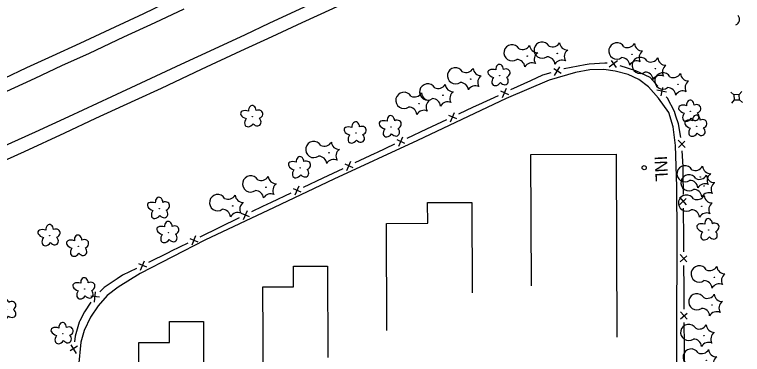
# Model space of a CAD drawing. Extents: x 588843 to 2552415, y 180129 to 269402.
# Drawn here: x 593421.1 to 593773.6, y 187938.5 to 188103.3 of the extents above; entities that cross this region are included whole.
import ezdxf

# ---------------------------------------------------------------- set-up
doc = ezdxf.new("R2010")
doc.units = 0
for name, color, linetype in [('Default', 7, 'Continuous'), ('E_BLD', 7, 'Continuous'), ('E_DRN', 7, 'Continuous'), ('E_DRN_Text', 7, 'Continuous'), ('E_DWY', 7, 'Continuous'), ('E_FEN_P', 7, 'Continuous'), ('E_LAND_Vegetation', 7, 'Continuous'), ('E_RDWY', 7, 'Continuous'), ('E_RDWY_Gravel', 7, 'Continuous'), ('E_UTL_AG_Bold', 7, 'Continuous')]:
    doc.layers.add(name, color=color, linetype=linetype)

# ---------------------------------------------------------------- blocks, each defined once
blk = doc.blocks.new('DTRE')
at = {"layer": 'Default'}
blk.add_circle((-0.18, 0), 0.183, dxfattribs=at)
for centre, major_axis, ratio in [((-1.87, 5.32), (1.36, -4.98), 0.782863), ((4.06, 2.74), (-5.27, -2.93), 0.691916), ((-5.87, 0.15), (4.93, -0.12), 0.832022), ((-2.49, -5.24), (1.8, 4.86), 0.716896), ((3.54, -3.71), (-5.01, 4.58), 0.560249)]:
    blk.add_ellipse(centre, major_axis=major_axis, ratio=ratio, start_param=1.570796, end_param=4.712389, dxfattribs=at)
blk = doc.blocks.new('CTRE')
at = {"layer": 'Default'}
blk.add_circle((0, 0), 0.223, dxfattribs=at)
for centre, start, end in [((-11.97, 8.96), 280.2067, 5.97162), ((1.81, 14.92), 220.21132, 305.97623), ((13.83, 5.89), 160.21133, 245.97624), ((-13.83, -5.9), 340.21132, 65.97623), ((12.03, -9.04), 185.92721, 100.25111), ((-1.81, -14.93), 40.21133, 125.97624)]:
    blk.add_arc(centre, 7.87, start, end, dxfattribs=at)
blk = doc.blocks.new('CULV2')
at = {"layer": 'E_DRN'}
blk.add_arc((19.7, 14.8), 24.6, 216.8699, 323.1301, dxfattribs=at)
blk = doc.blocks.new('PED')
at = {"layer": 'Default'}
for p, q in [((-2.5, 2.5), (-5.33, 5.33)), ((2.5, 2.5), (5.33, 5.33)), ((-2.5, -2.5), (-5.33, -5.33)), ((2.5, -2.5), (5.33, -5.33))]:
    blk.add_line(p, q, dxfattribs=at)
blk.add_lwpolyline([(-2.5, -2.5), (2.5, -2.5), (2.5, 2.5), (-2.5, 2.5)], close=True, dxfattribs=at)
blk = doc.blocks.new('INLT_38')
at = {"layer": 'E_DRN_Text'}
blk.add_text('INL', height=12, dxfattribs=at).set_placement((-11.03, -6))

msp = doc.modelspace()

# ---------------------------------------------------------------- linework, layer by layer
at = {"layer": 'E_BLD'}
for points in [[(593671.39, 187971.86), (593671.13, 188035.51), (593712.46, 188035.68), (593712.81, 187946.87)], [(593601.38, 187950.19), (593601.15, 188002.09), (593621.17, 188002.18), (593621.12, 188012.15), (593642.47, 188012.24), (593642.66, 187968.48)], [(593541.59, 187922.43), (593541.42, 187971.31), (593556.2, 187971.36), (593556.17, 187981.35), (593572.64, 187981.4), (593572.79, 187937.03)], [(593481.51, 187894.33), (593481.28, 187944.27), (593496.19, 187944.33), (593496.14, 187954.5), (593512.56, 187954.57), (593512.76, 187908.95)]]:
    msp.add_lwpolyline(points, dxfattribs=at)
at = {"layer": 'E_DRN'}
msp.add_ellipse((593725.99, 188029.11), major_axis=(-0.936, 0.363), ratio=0.999898, dxfattribs=at)
at = {"layer": 'E_DWY'}
msp.add_lwpolyline([(593741.83, 187929.37), (593741.8, 187948.74), (593741.91, 187995.77), (593741.74, 188019.71), (593741.08, 188039.87), (593740.1, 188048.86), (593737.91, 188055.8), (593732.86, 188062.83), (593728.04, 188068.31), (593723.38, 188071.8), (593718.22, 188074.22), (593711.99, 188075.92), (593706.46, 188076.71), (593699.73, 188076.42), (593692.67, 188075.13), (593679.99, 188071.45), (593659.18, 188062.62), (593616.22, 188042.22), (593575.79, 188023.5), (593546.79, 188009.85), (593513.27, 187993.87), (593482, 187977.86), (593471.23, 187971.23), (593466.04, 187967.13), (593461.55, 187962.15), (593457.96, 187956.61), (593454.85, 187950.14), (593453.28, 187944.58), (593452.02, 187932.91)], dxfattribs=at)
at = {"layer": 'E_FEN_P'}
for p, q in [((593713.03, 188080.78), (593709.1, 188077.86)), ((593712.61, 188077.59), (593710.09, 188080.94)), ((593685.82, 188074.77), (593682.26, 188076.98)), ((593685.06, 188077.89), (593682.45, 188073.75)), ((593660.42, 188064.39), (593656.58, 188066.08)), ((593659.22, 188067.38), (593657.22, 188062.91)), ((593736.85, 188065.68), (593732.05, 188066.61)), ((593734.22, 188063.83), (593734.99, 188067.96)), ((593634.05, 188055.67), (593632.09, 188051.19)), ((593635.27, 188052.69), (593631.42, 188054.35)), ((593610.17, 188040.87), (593606.32, 188042.53)), ((593608.95, 188043.85), (593606.98, 188039.37)), ((593745.83, 188038.9), (593742.45, 188042.44)), ((593742.61, 188038.92), (593745.63, 188041.84)), ((593585.07, 188029.04), (593581.22, 188030.7)), ((593583.85, 188032.02), (593581.88, 188027.54)), ((593558.75, 188020.19), (593556.79, 188015.71)), ((593559.97, 188017.21), (593556.12, 188018.87)), ((593746.49, 188011.11), (593743.24, 188014.77)), ((593743.28, 188011.24), (593746.39, 188014.06)), ((593534.95, 188005.28), (593531.07, 188006.88)), ((593533.69, 188008.23), (593531.79, 188003.72)), ((593508.79, 187995.99), (593506.89, 187991.48)), ((593510.05, 187993.03), (593506.17, 187994.63)), ((593746.69, 187983.36), (593743.46, 187987.03)), ((593743.48, 187983.51), (593746.61, 187986.3)), ((593485.14, 187980.82), (593481.26, 187982.43)), ((593483.88, 187983.78), (593481.97, 187979.27)), ((593460.18, 187968.82), (593459.71, 187963.95)), ((593462.27, 187966.38), (593458.09, 187966.74)), ((593746.85, 187955.61), (593743.62, 187959.28)), ((593743.64, 187955.76), (593746.77, 187958.56)), ((593451.55, 187942.56), (593448.02, 187940.29)), ((593448.4, 187943.21), (593451.02, 187939.08))]:
    msp.add_line(p, q, dxfattribs=at)
for points in [[(593697.46, 188078.89), (593687.18, 188076.98), (593687.05, 188076.94)], [(593708, 188079.68), (593706.94, 188079.77), (593699.43, 188079.25), (593697.46, 188078.89)], [(593724.36, 188074.93), (593721.94, 188076.09), (593714.41, 188078.49)], [(593680.77, 188075.05), (593676.69, 188073.83), (593670.94, 188071.16)], [(593732.61, 188068.61), (593728.92, 188072.74), (593724.36, 188074.93)], [(593670.94, 188071.16), (593661.32, 188066.72)], [(593655.37, 188063.96), (593645.75, 188059.52)], [(593741.33, 188054.01), (593740.59, 188056.32), (593737.2, 188062.82), (593736.69, 188063.48)], [(593645.75, 188059.52), (593643.18, 188058.32), (593636.16, 188055.02)], [(593630.23, 188052.23), (593620.64, 188047.71)], [(593743.75, 188043.71), (593742.53, 188050.32), (593741.33, 188054.01)], [(593620.64, 188047.71), (593611.06, 188043.2)], [(593605.13, 188040.4), (593596.37, 188036.28), (593595.54, 188035.89)], [(593595.54, 188035.89), (593585.96, 188031.37)], [(593744.82, 188026.62), (593744.79, 188029.6), (593744.43, 188037.2)], [(593580.03, 188028.58), (593570.44, 188024.06)], [(593570.44, 188024.06), (593560.86, 188019.54)], [(593744.95, 188016.02), (593744.82, 188026.62)], [(593554.93, 188016.75), (593545.35, 188012.23)], [(593545.35, 188012.23), (593541.23, 188010.29), (593535.81, 188007.62)], [(593745.12, 187998.87), (593745.08, 188005.1), (593745.03, 188009.47)], [(593529.92, 188004.73), (593520.41, 188000.05)], [(593520.41, 188000.05), (593510.91, 187995.38)], [(593745.18, 187988.28), (593745.12, 187998.87)], [(593505.02, 187992.49), (593497, 187988.54), (593495.51, 187987.81)], [(593495.51, 187987.81), (593485.99, 187983.16)], [(593745.28, 187971.13), (593745.22, 187981.72)], [(593480.1, 187980.28), (593473.34, 187976.98), (593470.81, 187975.24)], [(593470.81, 187975.24), (593464.59, 187970.97), (593462.38, 187968.87)], [(593745.34, 187960.53), (593745.28, 187971.13)], [(593458.09, 187963.96), (593454.96, 187959.28), (593452.79, 187954.82)], [(593452.79, 187954.82), (593452.47, 187954.15), (593450.54, 187947.38), (593450.11, 187944.6)], [(593745.44, 187943.38), (593745.38, 187953.97)], [(593745.5, 187932.79), (593745.44, 187943.38)]]:
    msp.add_lwpolyline(points, dxfattribs=at)
at = {"layer": 'E_RDWY'}
for points in [[(593752.41, 188183.99), (593734.97, 188177.43), (593719.28, 188171.39), (593702.83, 188165.13), (593686.75, 188158.96), (593670.84, 188152.85), (593656.08, 188147.04), (593636.34, 188139.62), (593622.08, 188133.98), (593606.39, 188127.73), (593595.33, 188122.53), (593577.3, 188114.27), (593561.3, 188106.87), (593544.26, 188098.91), (593532.83, 188093.48), (593517.78, 188086.56), (593501.59, 188079.01), (593482.3, 188070.07), (593468.08, 188063.45), (593447.19, 188053.78), (593431.08, 188046.3), (593414.72, 188038.83)], [(593503.02, 188105.97), (593489.08, 188099.32), (593473.88, 188092.25), (593457.22, 188084.49), (593443.83, 188078.38), (593431.03, 188072.37), (593415.1, 188065.07)]]:
    msp.add_lwpolyline(points, dxfattribs=at)
at = {"layer": 'E_RDWY_Gravel'}
for points in [[(593680.23, 188197.49), (593679.94, 188197.39), (593666.65, 188191.49), (593653.34, 188186.04), (593640.19, 188180.83), (593625.45, 188174.06), (593610.04, 188166.94), (593598.2, 188161.18), (593585.94, 188155.62), (593573.66, 188149.84), (593553.98, 188140.8), (593546.28, 188137.29), (593539.89, 188134.23), (593528.22, 188127.92), (593518.91, 188122.75), (593511.76, 188118.83), (593502.27, 188113.58), (593493.31, 188108.39), (593483.56, 188103.68), (593467.22, 188096.06), (593452.76, 188089.29), (593439.4, 188083.15), (593426.93, 188077.44), (593416.12, 188072.34)], [(593753.68, 188181.11), (593738.16, 188175.41), (593719.58, 188168.16), (593705, 188162.42), (593692.98, 188156.71), (593676.15, 188149.08), (593659.11, 188141.18), (593640.47, 188132.77), (593619.59, 188125.29), (593605.54, 188120.19), (593590.8, 188113.55), (593575, 188106.04), (593560.21, 188099.2), (593545.68, 188092.45), (593530.56, 188085.51), (593511.53, 188076.69), (593492.13, 188067.52), (593479.33, 188061.56), (593460.33, 188052.93), (593445.36, 188045.83), (593425.71, 188036.76), (593412.44, 188030.78), (593397.11, 188023.55), (593368.54, 188010.26)]]:
    msp.add_lwpolyline(points, dxfattribs=at)

# ---------------------------------------------------------------- block references
at = {"layer": 'E_DRN', "xscale": 0.11901954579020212, "yscale": 0.11901954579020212, "rotation": 76.78394823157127}
msp.add_blockref('CULV2', (593770.45, 188098.25), dxfattribs=at)
at = {"layer": 'E_DRN_Text', "xscale": 0.49999999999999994, "yscale": 0.5, "rotation": -87.17004709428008}
msp.add_blockref('INLT_38', (593734.24, 188029.3), dxfattribs=at)
at = {"layer": 'E_LAND_Vegetation'}
for name, p, xscale, yscale, rotation in [('CTRE', (593683.93, 188084.42), 0.5000000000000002, 0.5, -155.27849407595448), ('CTRE', (593720.14, 188084.03), 0.5000000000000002, 0.5, -155.27849407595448), ('CTRE', (593669.37, 188083.13), 0.5000000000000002, 0.5, -155.27849407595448), ('CTRE', (593731.44, 188077.04), 0.5000000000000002, 0.5, -155.27849407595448), ('CTRE', (593642.01, 188071.98), 0.5000000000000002, 0.5, -155.27849407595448), ('DTRE', (593655.96, 188073.66), 0.5000000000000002, 0.5, -155.27849407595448), ('CTRE', (593742.41, 188069.5), 0.5000000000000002, 0.5, -155.27849407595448), ('CTRE', (593628.52, 188064.19), 0.5000000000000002, 0.5, -155.27849407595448), ('CTRE', (593617.02, 188060.11), 0.5000000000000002, 0.5, -155.27849407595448), ('DTRE', (593748.31, 188056.35), 0.5000000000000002, 0.5, -155.27849407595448), ('DTRE', (593536.24, 188053.72), 0.5000000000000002, 0.5, -155.27849407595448), ('DTRE', (593603.31, 188048.81), 0.5000000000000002, 0.5, -155.27849407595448), ('DTRE', (593751.27, 188049.08), 0.5000000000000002, 0.5, -155.27849407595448), ('DTRE', (593586.32, 188045.8), 0.5000000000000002, 0.5, -155.27849407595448), ('CTRE', (593573.39, 188036.27), 0.5000000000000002, 0.5, -155.27849407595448), ('DTRE', (593559.36, 188028.96), 0.5000000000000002, 0.5, -155.27849407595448), ('CTRE', (593753.11, 188024.51), 0.5000000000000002, 0.5, -155.27849407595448), ('CTRE', (593542.82, 188019.61), 0.5000000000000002, 0.5, -155.27849407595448), ('CTRE', (593755.03, 188020.18), 0.5000000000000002, 0.5, -155.27849407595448), ('CTRE', (593526.81, 188010.55), 0.5000000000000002, 0.5, -155.27849407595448), ('CTRE', (593753.88, 188010.34), 0.5000000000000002, 0.5, -155.27849407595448), ('DTRE', (593491.1, 188009.23), 0.5000000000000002, 0.5, -155.27849407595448), ('DTRE', (593757.13, 187998.88), 0.5000000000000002, 0.5, -155.27849407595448), ('DTRE', (593438.1, 187996.06), 0.5000000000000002, 0.5, -155.27849407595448), ('DTRE', (593495.6, 187997.57), 0.5000000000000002, 0.5, -155.27849407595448), ('DTRE', (593451.9, 187990.92), 0.5000000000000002, 0.5, -155.27849407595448), ('CTRE', (593760.01, 187975.97), 0.5000000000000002, 0.5, -155.27849407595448), ('DTRE', (593454.96, 187970.26), 0.5000000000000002, 0.5, -155.27849407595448), ('CTRE', (593758.82, 187962.5), 0.5000000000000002, 0.5, -155.27849407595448), ('DTRE', (593417.07, 187960.31), 0.5, 0.49999999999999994, -143.48607765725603), ('CTRE', (593754.89, 187947.63), 0.5000000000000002, 0.5, -155.27849407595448), ('DTRE', (593444.43, 187948.59), 0.5000000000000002, 0.5, -155.27849407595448), ('CTRE', (593756.07, 187935.71), 0.5000000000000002, 0.5, -155.27849407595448)]:
    msp.add_blockref(name, p, dxfattribs=dict(at, xscale=xscale, yscale=yscale, rotation=rotation))
at = {"layer": 'E_UTL_AG_Bold', "xscale": 0.49999999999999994, "yscale": 0.5, "rotation": -87.17004709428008}
msp.add_blockref('PED', (593770.77, 188063.19), dxfattribs=at)

doc.saveas('drawing.dxf')
